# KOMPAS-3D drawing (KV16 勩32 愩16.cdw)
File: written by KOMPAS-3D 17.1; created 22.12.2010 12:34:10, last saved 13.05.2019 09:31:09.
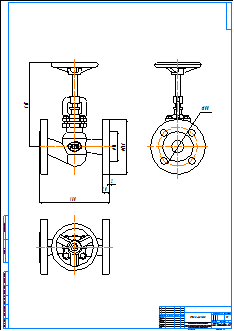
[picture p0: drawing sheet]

Title block, sheet 1: name: KV16 Ду32 Ру16; material: Внимание! Данный продукт является объектом авторского права ООО «Торговый Дом АДЛ». / Запрещается изменение, копирование, распространение / (в том числе путем копирования на другие сайты и ресурсы в Интернете) / или любое иное использование информации и объектов без предварительного / согласия правообладателя (ООО «Торговый Дом АДЛ»).; scale: 1:1; sheets: 1; organisation: ООО "Торговый дом АДЛ"; sheet format: A1; stored path: \\adlc.lan\data\АДЛ_ПКД\3D-модели\ADL production\Вентили ГРАНВЕНТ\KV16\KOMPAS 2D\KV16 Ду32 Ру16.cdw

Views: Спереди 1, Проекционный вид 2, Вид 5
Dimensions and other numbers on the sheet: 76; 140; 2; 20; 180; 100; 215; 1:1; 1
